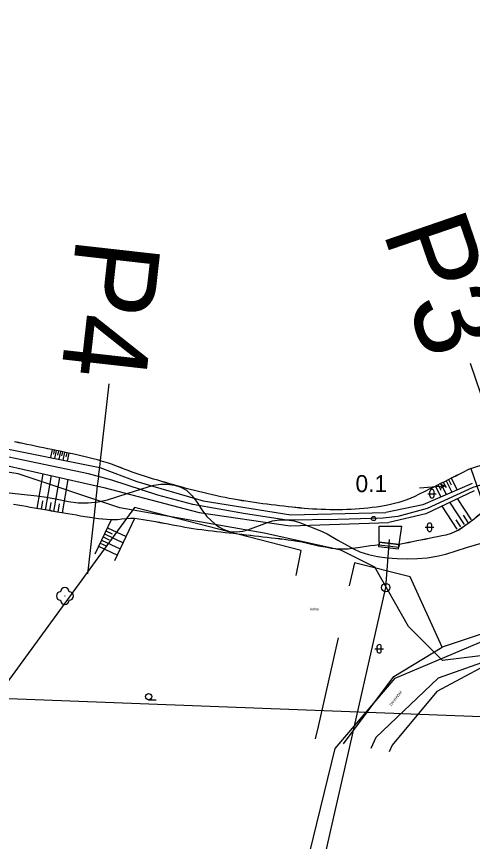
# Model space of a CAD drawing. Extents: x -737422 to -734235, y -1145631 to -1142623.
# Drawn here: x -736944.2 to -736890.5, y -1144842.3 to -1144745.2 of the extents above; entities that cross this region are included whole.
import ezdxf

# ---------------------------------------------------------------- set-up
doc = ezdxf.new("R2010")
doc.units = 0
for name, color, linetype in [('Vrstva 1', 7, 'Continuous'), ('Vrstva 2', 7, 'Continuous'), ('Vrstva 20', 7, 'Continuous'), ('Vrstva 21', 7, 'Continuous'), ('Vrstva 22', 7, 'Continuous'), ('Vrstva 3', 7, 'Continuous'), ('Vrstva 30', 7, 'Continuous'), ('Vrstva 40', 7, 'Continuous'), ('Vrstva 41', 7, 'Continuous'), ('Vrstva 6', 7, 'Continuous'), ('Vrstva 7', 7, 'Continuous'), ('Vrstva 8', 7, 'Continuous'), ('Vrstva 9', 7, 'Continuous')]:
    doc.layers.add(name, color=color, linetype=linetype)

# ---------------------------------------------------------------- blocks, each defined once
blk = doc.blocks.new('1.050')
at = {"layer": 'Vrstva 1'}
for radius in [0.5, 0.001]:
    blk.add_circle((0, 0), radius, dxfattribs=at)
blk = doc.blocks.new('6.200')
at = {"layer": 'Vrstva 1'}
blk.add_circle((0, 0), 1, dxfattribs=at)
blk = doc.blocks.new('3.040')
at = {"layer": 'Vrstva 1'}
blk.add_line((0, -0.75), (1.75, -0.75), dxfattribs=at)
blk.add_circle((0, 0), 0.75, dxfattribs=at)
blk = doc.blocks.new('3.160')
at = {"layer": 'Vrstva 1'}
for p, q in [((-1, 0), (1, 0)), ((-0.5, -0.5), (-0.5, 0.5)), ((0.5, -0.5), (0.5, 0.5))]:
    blk.add_line(p, q, dxfattribs=at)
for centre, start, end in [((0, 0.5), 0, 180), ((0, -0.5), 180, 360)]:
    blk.add_arc(centre, 0.5, start, end, dxfattribs=at)
blk = doc.blocks.new('3.130')
at = {"layer": 'Vrstva 1'}
blk.add_circle((0, 0), 0.001, dxfattribs=at)
for centre, start, end in [((0, 1), 0, 180), ((-1, 0), 90, 270), ((1, 0), 270, 90), ((0, -1), 180, 360)]:
    blk.add_arc(centre, 1, start, end, dxfattribs=at)
blk = doc.blocks.new('8.021')
at = {"layer": 'Vrstva 1'}
blk.add_line((-3, 0), (3, 0), dxfattribs=at)
blk.add_lwpolyline([(2, 0.5), (3, 0), (2, -0.5)], dxfattribs=at)

msp = doc.modelspace()

# ---------------------------------------------------------------- linework, layer by layer
at = {"layer": 'Vrstva 1'}
for points in [[(-736946.557, -1144801.069), (-736941.778, -1144801.588), (-736940.647, -1144801.748), (-736939.578, -1144801.944), (-736938.076, -1144802.269), (-736936.923, -1144802.406)], [(-736936.923, -1144802.406), (-736935.748, -1144802.422), (-736934.588, -1144802.318), (-736933.483, -1144802.088), (-736931.174, -1144801.315), (-736928.662, -1144800.526), (-736928.011, -1144800.348), (-736927.206, -1144800.229), (-736926.39, -1144800.223), (-736925.593, -1144800.332), (-736924.846, -1144800.563), (-736924.181, -1144800.933), (-736923.495, -1144801.594), (-736922.914, -1144802.394), (-736922.363, -1144803.236), (-736921.768, -1144804.025), (-736921.32, -1144804.48), (-736920.845, -1144804.885), (-736920.359, -1144805.248), (-736919.846, -1144805.542), (-736919.095, -1144805.782), (-736918.301, -1144805.853), (-736917.512, -1144805.764), (-736916.946, -1144805.602), (-736914.64, -1144804.743), (-736914.048, -1144804.556), (-736913.208, -1144804.418), (-736912.337, -1144804.414), (-736911.474, -1144804.549), (-736910.851, -1144804.74), (-736908.466, -1144805.663), (-736907.599, -1144806.079), (-736906.361, -1144806.807), (-736904.419, -1144807.861), (-736903.735, -1144808.177), (-736902.739, -1144808.508), (-736901.66, -1144808.742), (-736900.523, -1144808.897), (-736899.35, -1144808.985), (-736898.16, -1144809.011), (-736896.972, -1144808.978), (-736895.803, -1144808.884), (-736894.674, -1144808.72), (-736893.605, -1144808.475), (-736891.185, -1144807.689), (-736889.319, -1144807.129)]]:
    msp.add_lwpolyline(points, dxfattribs=at)
at = {"layer": 'Vrstva 2'}
msp.add_lwpolyline([(-736838.94, -1144743.71), (-736840.58, -1144747.75), (-736844.39, -1144755.61), (-736848.81, -1144763.32), (-736858.24, -1144778.35), (-736864.33, -1144788), (-736868, -1144792.54), (-736868.74, -1144793.25), (-736870.42, -1144794.38), (-736872.26, -1144795.22), (-736876.13, -1144796.44), (-736887.1, -1144799.6), (-736890.46, -1144800.61), (-736895.84, -1144803.1), (-736899.26, -1144804.04), (-736901.02, -1144804.24), (-736906.35, -1144804.39), (-736912.33, -1144804.46), (-736917.21, -1144803.72), (-736923.41, -1144802.63), (-736927.55, -1144801.53), (-736932.98, -1144799.76), (-736935.72, -1144798.99), (-736947.76, -1144796.51)], dxfattribs=at)
at = {"layer": 'Vrstva 20'}
for points in [[(-736935.63, -1144797.12), (-736936.12, -1144797), (-736936.6, -1144796.89), (-736937.09, -1144796.77), (-736937.58, -1144796.66), (-736938.07, -1144796.56), (-736938.56, -1144796.45), (-736939.05, -1144796.35), (-736939.54, -1144796.25), (-736940.03, -1144796.15), (-736940.52, -1144796.05), (-736941.01, -1144795.95), (-736941.5, -1144795.85), (-736941.99, -1144795.75), (-736942.48, -1144795.65), (-736942.97, -1144795.55), (-736943.46, -1144795.44), (-736943.94, -1144795.34), (-736944.43, -1144795.23)], [(-736946.95, -1144795.74), (-736934.36, -1144798.26)], [(-736890.66, -1144798.37), (-736891.11, -1144798.59), (-736891.55, -1144798.82), (-736892, -1144799.04), (-736892.45, -1144799.26), (-736892.9, -1144799.49), (-736893.34, -1144799.71), (-736893.79, -1144799.94), (-736894.24, -1144800.16), (-736894.69, -1144800.38), (-736895.13, -1144800.61), (-736895.58, -1144800.83), (-736896.03, -1144801.05), (-736896.84, -1144801.46), (-736897.29, -1144801.68), (-736897.75, -1144801.87), (-736898.22, -1144802.05), (-736898.69, -1144802.22), (-736899.17, -1144802.37), (-736899.66, -1144802.5), (-736900.15, -1144802.62), (-736900.64, -1144802.72), (-736901.3, -1144802.84), (-736901.8, -1144802.92), (-736902.29, -1144802.98), (-736902.79, -1144803.04), (-736903.29, -1144803.09), (-736903.79, -1144803.14), (-736904.29, -1144803.17), (-736904.79, -1144803.2), (-736905.3, -1144803.22), (-736905.8, -1144803.23), (-736906.3, -1144803.24), (-736906.8, -1144803.24), (-736907.3, -1144803.23), (-736907.81, -1144803.22), (-736908.31, -1144803.2), (-736908.81, -1144803.18), (-736909.31, -1144803.15), (-736909.81, -1144803.12), (-736910.31, -1144803.08), (-736910.81, -1144803.03), (-736911.71, -1144802.94), (-736912.21, -1144802.89), (-736912.7, -1144802.83), (-736913.2, -1144802.77), (-736913.69, -1144802.71), (-736914.19, -1144802.65), (-736914.69, -1144802.59), (-736915.18, -1144802.53), (-736915.68, -1144802.46), (-736916.17, -1144802.39), (-736916.67, -1144802.32), (-736917.16, -1144802.24), (-736917.65, -1144802.17), (-736918.15, -1144802.08), (-736918.64, -1144802), (-736919.13, -1144801.91), (-736919.63, -1144801.81), (-736920.12, -1144801.71), (-736920.61, -1144801.61), (-736921.1, -1144801.5), (-736921.77, -1144801.34), (-736922.26, -1144801.22), (-736922.75, -1144801.1), (-736923.23, -1144800.97), (-736923.72, -1144800.85), (-736924.2, -1144800.72), (-736924.68, -1144800.59), (-736925.16, -1144800.45), (-736925.65, -1144800.32), (-736926.13, -1144800.18), (-736926.61, -1144800.05), (-736927.08, -1144799.91), (-736927.56, -1144799.76), (-736928.04, -1144799.62), (-736928.52, -1144799.47), (-736928.99, -1144799.32), (-736929.61, -1144799.13), (-736930.09, -1144798.97), (-736930.56, -1144798.8), (-736931.02, -1144798.63), (-736931.49, -1144798.45), (-736931.96, -1144798.27), (-736932.43, -1144798.09), (-736932.9, -1144797.92), (-736933.37, -1144797.75), (-736934.18, -1144797.5), (-736934.66, -1144797.37), (-736935.15, -1144797.24), (-736935.63, -1144797.12)], [(-736890.66, -1144798.37), (-736886.95, -1144797.15)], [(-736947.85, -1144797.46), (-736933.89, -1144800.62)], [(-736934.36, -1144798.26), (-736930.01, -1144799.9)], [(-736890.66, -1144798.37), (-736889.34, -1144802.22)], [(-736930.01, -1144799.9), (-736922.22, -1144802.18)], [(-736890.52, -1144800.14), (-736896.33, -1144802.65)], [(-736933.89, -1144800.62), (-736922.67, -1144803.55)], [(-736890.29, -1144801), (-736895.99, -1144803.72)], [(-736930.3, -1144802.96), (-736954.96, -1144836.76)], [(-736901.49, -1144807.36), (-736901.99, -1144807.43), (-736902.48, -1144807.5), (-736902.98, -1144807.57), (-736903.47, -1144807.64), (-736903.97, -1144807.71), (-736904.64, -1144807.81), (-736905.14, -1144807.86), (-736905.63, -1144807.88), (-736906.13, -1144807.87), (-736906.62, -1144807.84), (-736907.12, -1144807.78), (-736907.61, -1144807.7), (-736908.11, -1144807.61), (-736908.6, -1144807.51), (-736909.1, -1144807.4), (-736909.6, -1144807.29), (-736910.09, -1144807.18), (-736910.59, -1144807.07), (-736911.08, -1144806.97), (-736911.58, -1144806.89), (-736912.18, -1144806.8), (-736912.68, -1144806.74), (-736913.17, -1144806.68), (-736913.67, -1144806.62), (-736914.17, -1144806.57), (-736914.66, -1144806.51), (-736915.16, -1144806.45), (-736915.66, -1144806.39), (-736916.15, -1144806.34), (-736916.65, -1144806.28), (-736917.15, -1144806.22), (-736917.64, -1144806.16), (-736918.14, -1144806.11), (-736918.64, -1144806.05), (-736919.13, -1144805.99), (-736919.63, -1144805.94), (-736920.13, -1144805.88), (-736920.62, -1144805.82), (-736921.12, -1144805.76), (-736921.62, -1144805.7), (-736922.38, -1144805.61), (-736922.88, -1144805.55), (-736923.37, -1144805.47), (-736923.86, -1144805.4), (-736924.36, -1144805.31), (-736924.85, -1144805.22), (-736925.34, -1144805.13), (-736925.83, -1144805.04), (-736926.32, -1144804.94), (-736926.82, -1144804.85), (-736927.31, -1144804.76), (-736927.8, -1144804.66), (-736928.29, -1144804.58), (-736928.78, -1144804.49), (-736929.28, -1144804.42), (-736929.77, -1144804.34), (-736930.28, -1144804.28), (-736930.78, -1144804.26), (-736931.28, -1144804.3), (-736931.78, -1144804.36), (-736932.28, -1144804.42), (-736933.05, -1144804.44), (-736933.55, -1144804.4), (-736934.04, -1144804.35), (-736934.54, -1144804.29), (-736935.04, -1144804.23), (-736935.53, -1144804.16), (-736936.15, -1144804.06), (-736936.65, -1144803.98), (-736937.14, -1144803.89), (-736937.63, -1144803.81), (-736938.13, -1144803.72), (-736938.62, -1144803.64), (-736939.12, -1144803.55), (-736939.61, -1144803.47), (-736940.1, -1144803.38), (-736940.6, -1144803.3), (-736941.09, -1144803.21), (-736941.58, -1144803.13), (-736942.07, -1144803.04), (-736942.57, -1144802.96), (-736943.06, -1144802.87), (-736943.55, -1144802.78), (-736944.04, -1144802.69), (-736944.53, -1144802.6)], [(-736911.24, -1144810.96), (-736910.65, -1144808.02), (-736930.3, -1144802.96)], [(-736922.22, -1144802.18), (-736911.86, -1144803.82)], [(-736896.33, -1144802.65), (-736900.68, -1144803.58)], [(-736922.67, -1144803.55), (-736911.95, -1144805.14)], [(-736911.86, -1144803.82), (-736900.68, -1144803.58)], [(-736895.99, -1144803.72), (-736900.35, -1144804.74)], [(-736888.82, -1144803.24), (-736889.24, -1144803.52), (-736889.65, -1144803.82), (-736890.06, -1144804.13), (-736890.46, -1144804.45), (-736890.86, -1144804.76), (-736891.27, -1144805.07), (-736891.69, -1144805.36), (-736892.11, -1144805.62), (-736892.55, -1144805.85), (-736893, -1144806.05), (-736893.62, -1144806.22), (-736894.11, -1144806.32), (-736894.6, -1144806.42), (-736895.09, -1144806.52), (-736895.58, -1144806.62), (-736896.07, -1144806.72), (-736896.56, -1144806.82), (-736897.05, -1144806.91), (-736897.54, -1144807.01), (-736898.03, -1144807.11), (-736898.52, -1144807.21), (-736899.11, -1144807.33)], [(-736933.05, -1144804.44), (-736934.96, -1144808.45)], [(-736930.28, -1144804.28), (-736932.63, -1144809.24)], [(-736911.95, -1144805.14), (-736900.35, -1144804.74)], [(-736901.46, -1144805.18), (-736898.81, -1144805.15)], [(-736901.46, -1144807.06), (-736901.46, -1144805.18)], [(-736899.11, -1144807.33), (-736898.81, -1144805.15)], [(-736901.49, -1144807.07), (-736901.55, -1144807.56), (-736899.18, -1144807.83), (-736899.14, -1144807.33), (-736901.49, -1144807.07)], [(-736901.46, -1144807.06), (-736901.49, -1144807.36)], [(-736901.49, -1144807.36), (-736899.14, -1144807.63)], [(-736901.46, -1144807.06), (-736899.11, -1144807.33)], [(-736899.11, -1144807.33), (-736899.14, -1144807.63)], [(-736894.05, -1144819.43), (-736897.81, -1144811.14), (-736904.37, -1144809.48), (-736905.01, -1144812.2)], [(-736880.96, -1144815.92), (-736885.21, -1144816.47), (-736894.05, -1144819.43)], [(-736920.4, -1144878.06), (-736916.51, -1144871.64), (-736906.66, -1144831.34), (-736899.59, -1144823.06), (-736888.63, -1144818.43), (-736854.34, -1144829.36), (-736819.202, -1144837.154)], [(-736908.97, -1144830.2), (-736908.63, -1144828.75), (-736906.26, -1144818.31)], [(-736905.66, -1144830.78), (-736899.73, -1144822.85), (-736894.05, -1144819.43)], [(-736862.48, -1144826.23), (-736862.98, -1144825.23), (-736866.76, -1144822.43), (-736874.46, -1144819.59), (-736880.16, -1144818.92), (-736884.21, -1144819.43), (-736894.52, -1144823.06), (-736901.86, -1144830.06), (-736902.45, -1144831.35)], [(-736889.1, -1144821.66), (-736894.68, -1144824.63), (-736899.95, -1144830.94), (-736900.31, -1144831.73)]]:
    msp.add_lwpolyline(points, dxfattribs=at)
at = {"layer": 'Vrstva 21'}
for points in [[(-736939.99, -1144796.16), (-736940.19, -1144797.09)], [(-736939.75, -1144796.21), (-736939.85, -1144796.7)], [(-736939.5, -1144796.26), (-736939.7, -1144797.19)], [(-736939.26, -1144796.31), (-736939.36, -1144796.8)], [(-736939.01, -1144796.36), (-736939.21, -1144797.29)], [(-736938.77, -1144796.41), (-736938.87, -1144796.9)], [(-736938.52, -1144796.46), (-736938.72, -1144797.39)], [(-736938.28, -1144796.52), (-736938.38, -1144797)], [(-736938.03, -1144796.57), (-736938.22, -1144797.49)], [(-736941.75, -1144803.1), (-736941.04, -1144799)], [(-736940.76, -1144803.27), (-736940.07, -1144799.22)], [(-736939.78, -1144803.44), (-736939.09, -1144799.44)], [(-736938.79, -1144803.61), (-736938.11, -1144799.67)], [(-736894.23, -1144800.15), (-736893.58, -1144801.46)], [(-736893.92, -1144800), (-736893.6, -1144800.62)], [(-736893.6, -1144799.84), (-736892.93, -1144801.18)], [(-736893.29, -1144799.68), (-736892.98, -1144800.31)], [(-736892.98, -1144799.53), (-736892.29, -1144800.9)], [(-736894.85, -1144800.47), (-736894.22, -1144801.74)], [(-736894.54, -1144800.31), (-736894.23, -1144800.94)], [(-736890.59, -1144804.44), (-736892.23, -1144801.93)], [(-736941.26, -1144803.18), (-736941.09, -1144802.2)], [(-736940.27, -1144803.35), (-736940.1, -1144802.37)], [(-736939.29, -1144803.52), (-736939.12, -1144802.54)], [(-736892.27, -1144805.54), (-736894.06, -1144802.8)], [(-736891.43, -1144804.99), (-736893.14, -1144802.36)], [(-736891.01, -1144804.72), (-736891.56, -1144803.88)], [(-736891.85, -1144805.26), (-736892.4, -1144804.43)], [(-736933.66, -1144805.71), (-736932.93, -1144806.06)], [(-736933.49, -1144805.35), (-736931.28, -1144806.4)], [(-736934.17, -1144806.8), (-736931.97, -1144807.85)], [(-736934, -1144806.44), (-736933.28, -1144806.78)], [(-736933.83, -1144806.08), (-736931.63, -1144807.12)], [(-736934.52, -1144807.52), (-736932.31, -1144808.57)], [(-736934.35, -1144807.16), (-736933.62, -1144807.5)]]:
    msp.add_lwpolyline(points, dxfattribs=at)
at = {"layer": 'Vrstva 3'}
for points in [[(-736935.63, -1144797.119), (-736936.116, -1144797), (-736936.603, -1144796.885), (-736937.09, -1144796.773), (-736937.578, -1144796.664), (-736938.067, -1144796.558), (-736938.556, -1144796.453), (-736939.045, -1144796.351), (-736939.535, -1144796.249), (-736940.026, -1144796.149), (-736940.516, -1144796.049), (-736941.006, -1144795.949), (-736941.497, -1144795.85), (-736941.987, -1144795.75), (-736942.477, -1144795.648), (-736942.967, -1144795.546), (-736943.456, -1144795.442), (-736943.944, -1144795.336), (-736944.433, -1144795.227)], [(-736890.66, -1144798.37), (-736891.107, -1144798.594), (-736891.554, -1144798.817), (-736892.002, -1144799.041), (-736892.449, -1144799.264), (-736892.896, -1144799.488), (-736893.343, -1144799.712), (-736893.79, -1144799.935), (-736894.238, -1144800.159), (-736894.685, -1144800.382), (-736895.132, -1144800.606), (-736895.579, -1144800.83), (-736896.027, -1144801.053), (-736896.84, -1144801.46), (-736897.292, -1144801.675), (-736897.751, -1144801.872), (-736898.219, -1144802.053), (-736898.693, -1144802.217), (-736899.172, -1144802.365), (-736899.657, -1144802.499), (-736900.146, -1144802.617), (-736900.638, -1144802.722), (-736901.3, -1144802.84), (-736901.797, -1144802.915), (-736902.294, -1144802.982), (-736902.793, -1144803.041), (-736903.293, -1144803.092), (-736903.793, -1144803.135), (-736904.293, -1144803.17), (-736904.794, -1144803.198), (-736905.296, -1144803.218), (-736905.798, -1144803.232), (-736906.299, -1144803.239), (-736906.801, -1144803.239), (-736907.303, -1144803.233), (-736907.805, -1144803.221), (-736908.306, -1144803.203), (-736908.807, -1144803.18), (-736909.308, -1144803.151), (-736909.808, -1144803.116), (-736910.307, -1144803.077), (-736910.805, -1144803.032), (-736911.71, -1144802.94), (-736912.206, -1144802.885), (-736912.702, -1144802.829), (-736913.198, -1144802.772), (-736913.694, -1144802.713), (-736914.19, -1144802.653), (-736914.685, -1144802.591), (-736915.181, -1144802.527), (-736915.676, -1144802.46), (-736916.171, -1144802.391), (-736916.665, -1144802.319), (-736917.16, -1144802.244), (-736917.654, -1144802.165), (-736918.147, -1144802.083), (-736918.64, -1144801.997), (-736919.133, -1144801.907), (-736919.625, -1144801.812), (-736920.117, -1144801.713), (-736920.608, -1144801.608), (-736921.098, -1144801.499), (-736921.77, -1144801.34), (-736922.258, -1144801.219), (-736922.746, -1144801.097), (-736923.231, -1144800.972), (-736923.716, -1144800.846), (-736924.2, -1144800.717), (-736924.682, -1144800.587), (-736925.164, -1144800.454), (-736925.645, -1144800.32), (-736926.125, -1144800.184), (-736926.605, -1144800.045), (-736927.083, -1144799.905), (-736927.562, -1144799.763), (-736928.04, -1144799.619), (-736928.517, -1144799.472), (-736928.994, -1144799.324), (-736929.61, -1144799.13), (-736930.085, -1144798.972), (-736930.556, -1144798.804), (-736931.024, -1144798.628), (-736931.491, -1144798.448), (-736931.958, -1144798.267), (-736932.426, -1144798.089), (-736932.895, -1144797.916), (-736933.367, -1144797.751), (-736934.18, -1144797.5), (-736934.662, -1144797.368), (-736935.146, -1144797.241), (-736935.63, -1144797.119)], [(-736890.66, -1144798.37), (-736886.95, -1144797.15)], [(-736901.49, -1144807.36), (-736901.985, -1144807.431), (-736902.48, -1144807.503), (-736902.975, -1144807.575), (-736903.47, -1144807.646), (-736903.965, -1144807.717), (-736904.64, -1144807.81), (-736905.135, -1144807.86), (-736905.63, -1144807.877), (-736906.126, -1144807.866), (-736906.621, -1144807.829), (-736907.116, -1144807.771), (-736907.612, -1144807.696), (-736908.108, -1144807.606), (-736908.603, -1144807.505), (-736909.099, -1144807.398), (-736909.595, -1144807.287), (-736910.09, -1144807.177), (-736910.586, -1144807.071), (-736911.082, -1144806.972), (-736911.578, -1144806.885), (-736912.18, -1144806.8), (-736912.676, -1144806.741), (-736913.172, -1144806.682), (-736913.668, -1144806.624), (-736914.165, -1144806.566), (-736914.661, -1144806.508), (-736915.158, -1144806.451), (-736915.654, -1144806.393), (-736916.151, -1144806.336), (-736916.648, -1144806.279), (-736917.145, -1144806.222), (-736917.642, -1144806.164), (-736918.139, -1144806.107), (-736918.636, -1144806.05), (-736919.133, -1144805.992), (-736919.63, -1144805.935), (-736920.127, -1144805.877), (-736920.624, -1144805.819), (-736921.12, -1144805.76), (-736921.617, -1144805.701), (-736922.38, -1144805.61), (-736922.876, -1144805.546), (-736923.37, -1144805.474), (-736923.864, -1144805.396), (-736924.357, -1144805.312), (-736924.849, -1144805.224), (-736925.341, -1144805.132), (-736925.832, -1144805.039), (-736926.324, -1144804.944), (-736926.815, -1144804.849), (-736927.307, -1144804.756), (-736927.799, -1144804.664), (-736928.291, -1144804.576), (-736928.784, -1144804.493), (-736929.278, -1144804.415), (-736929.773, -1144804.344), (-736930.28, -1144804.28), (-736930.778, -1144804.26), (-736931.277, -1144804.298), (-736931.777, -1144804.363), (-736932.277, -1144804.424), (-736933.05, -1144804.44), (-736933.547, -1144804.397), (-736934.044, -1144804.348), (-736934.541, -1144804.292), (-736935.037, -1144804.23), (-736935.533, -1144804.159), (-736936.15, -1144804.06), (-736936.645, -1144803.975), (-736937.139, -1144803.89), (-736937.633, -1144803.806), (-736938.128, -1144803.721), (-736938.622, -1144803.637), (-736939.115, -1144803.553), (-736939.609, -1144803.469), (-736940.102, -1144803.384), (-736940.596, -1144803.299), (-736941.089, -1144803.214), (-736941.581, -1144803.129), (-736942.074, -1144803.043), (-736942.566, -1144802.956), (-736943.058, -1144802.869), (-736943.55, -1144802.781), (-736944.042, -1144802.692), (-736944.533, -1144802.602)], [(-736888.82, -1144803.24), (-736889.24, -1144803.517), (-736889.651, -1144803.815), (-736890.056, -1144804.127), (-736890.459, -1144804.446), (-736890.863, -1144804.762), (-736891.271, -1144805.068), (-736891.686, -1144805.358), (-736892.11, -1144805.622), (-736892.548, -1144805.854), (-736893.001, -1144806.045), (-736893.62, -1144806.22), (-736894.11, -1144806.319), (-736894.6, -1144806.418), (-736895.09, -1144806.517), (-736895.58, -1144806.616), (-736896.07, -1144806.715), (-736896.56, -1144806.815), (-736897.051, -1144806.914), (-736897.541, -1144807.013), (-736898.031, -1144807.112), (-736898.521, -1144807.211), (-736899.11, -1144807.33)], [(-736901.49, -1144807.36), (-736899.14, -1144807.63)], [(-736899.11, -1144807.33), (-736899.14, -1144807.63)]]:
    msp.add_lwpolyline(points, dxfattribs=at)
at = {"layer": 'Vrstva 30'}
for points in [[(-737312.25, -1144551.23), (-737277.23, -1144584.21), (-737291.65, -1144635.73), (-737173.72, -1144683.14), (-737162.39, -1144723.33), (-737091.6, -1144776.48), (-737004.14, -1144811.1), (-736946.11, -1144825.41), (-736889.46, -1144827.57), (-736808.94, -1144821.316)], [(-736886, -1144820), (-736894, -1144821), (-736898, -1144817), (-736902, -1144810), (-736906, -1144808), (-736915, -1144806), (-736932, -1144803), (-736944, -1144799), (-736957, -1144797)]]:
    msp.add_lwpolyline(points, dxfattribs=at)
at = {"layer": 'Vrstva 40'}
for points in [[(-736900.7, -1144812.4), (-736900.24, -1144806.73)], [(-736911.49, -1144860.04), (-736906.81, -1144839.39), (-736905.38, -1144833.05), (-736900.7, -1144812.4)]]:
    msp.add_lwpolyline(points, dxfattribs=at)
at = {"layer": 'Vrstva 8'}
for points in [[(-736890.77, -1144785.98), (-736888.36, -1144793.02), (-736886.95, -1144797.15), (-736886.44, -1144798.63), (-736886.21, -1144799.34), (-736886.19, -1144799.41), (-736885.97, -1144800.03), (-736885.63, -1144801), (-736883.96, -1144805.87), (-736882.26, -1144810.82)], [(-736933.33, -1144788.43), (-736934.34, -1144797.45), (-736934.43, -1144798.24), (-736934.52, -1144799.06), (-736934.55, -1144799.32), (-736934.67, -1144800.43), (-736935.1, -1144804.21), (-736935.84, -1144810.79)]]:
    msp.add_lwpolyline(points, dxfattribs=at)

# ---------------------------------------------------------------- block references
at = {"layer": 'Vrstva 20', "xscale": 0.5, "yscale": 0.5, "rotation": 4.238070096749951}
msp.add_blockref('8.021', (-736895.23, -1144800.54), dxfattribs=at)
at = {"layer": 'Vrstva 20', "xscale": 0.5, "yscale": 0.5}
for name, p in [('3.160', (-736895.25, -1144801.35)), ('3.160', (-736895.54, -1144805.3)), ('3.130', (-736938.49, -1144813.39)), ('6.200', (-736900.7, -1144812.4)), ('3.160', (-736901.47, -1144819.6)), ('3.040', (-736928.63, -1144825.24))]:
    msp.add_blockref(name, p, dxfattribs=at)
at = {"layer": 'Vrstva 41', "xscale": 0.5, "yscale": 0.5}
msp.add_blockref('6.200', (-736900.7, -1144812.4), dxfattribs=at)
at = {"layer": 'Vrstva 6', "xscale": 0.5, "yscale": 0.5}
msp.add_blockref('1.050', (-736902.13, -1144804.27), dxfattribs=at)

# ---------------------------------------------------------------- texts
at = {"layer": 'Vrstva 22'}
msp.add_text('kolna', height=0.3, dxfattribs=at).set_placement((-736909.58, -1144815.08))
msp.add_text('ZAHRADNÍ', height=0.3, rotation=52.17, dxfattribs=at).set_placement((-736900.06, -1144826.38))
at = {"layer": 'Vrstva 7'}
msp.add_text('0.1', height=2, dxfattribs=at).set_placement((-736904.26, -1144801.16))
at = {"layer": 'Vrstva 9'}
for s, rotation, p in [('P3', 288.954, (-736901.1, -1144770.46)), ('P4', 263.583, (-736937.11, -1144770.96))]:
    msp.add_text(s, height=10, rotation=rotation, dxfattribs=at).set_placement(p)

doc.saveas('drawing.dxf')
